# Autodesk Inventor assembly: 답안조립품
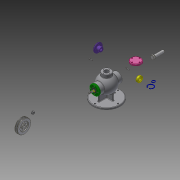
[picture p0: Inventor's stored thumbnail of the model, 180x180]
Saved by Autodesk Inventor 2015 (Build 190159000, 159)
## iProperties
Created: 2020-08
Part Number: 답안조립품
Document SubType Name: Assembly
Designer: 1019876
Author: 1019876
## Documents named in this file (18)
- C:\Users\1019876\Desktop\700806V1038\답안조립품.iam
- C:\Users\1019876\Desktop\700806V1038\V-벨트풀리.ipt
- C:\Users\1019876\Desktop\700806V1038\너트 M8.ipt
- C:\Users\1019876\Desktop\700806V1038\뒤커버.ipt
- C:\Users\1019876\Desktop\700806V1038\멈춤링 15x1.ipt
- C:\Users\1019876\Desktop\700806V1038\멈춤링 35x1.6.ipt
- 멈춤링 35x1.6.ipt
- C:\Users\1019876\Desktop\700806V1038\베어링 6202.ipt
- 베어링 6202.ipt
- C:\Users\1019876\Desktop\700806V1038\본체.ipt
- C:\Users\1019876\Desktop\700806V1038\볼트 M4.ipt
- C:\Users\1019876\Desktop\700806V1038\상부커버.ipt
- C:\Users\1019876\Desktop\700806V1038\슬라이드.ipt
- C:\Users\1019876\Desktop\700806V1038\앞커버.ipt
- C:\Users\1019876\Desktop\700806V1038\오일 실 15 30 7.ipt
- C:\Users\1019876\Desktop\700806V1038\칼라.ipt
- C:\Users\1019876\Desktop\700806V1038\키 3x3x12.ipt
- C:\Users\1019876\Desktop\700806V1038\편심축.ipt
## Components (1 placed, 1 different names)
1. V-벨트풀리:1
